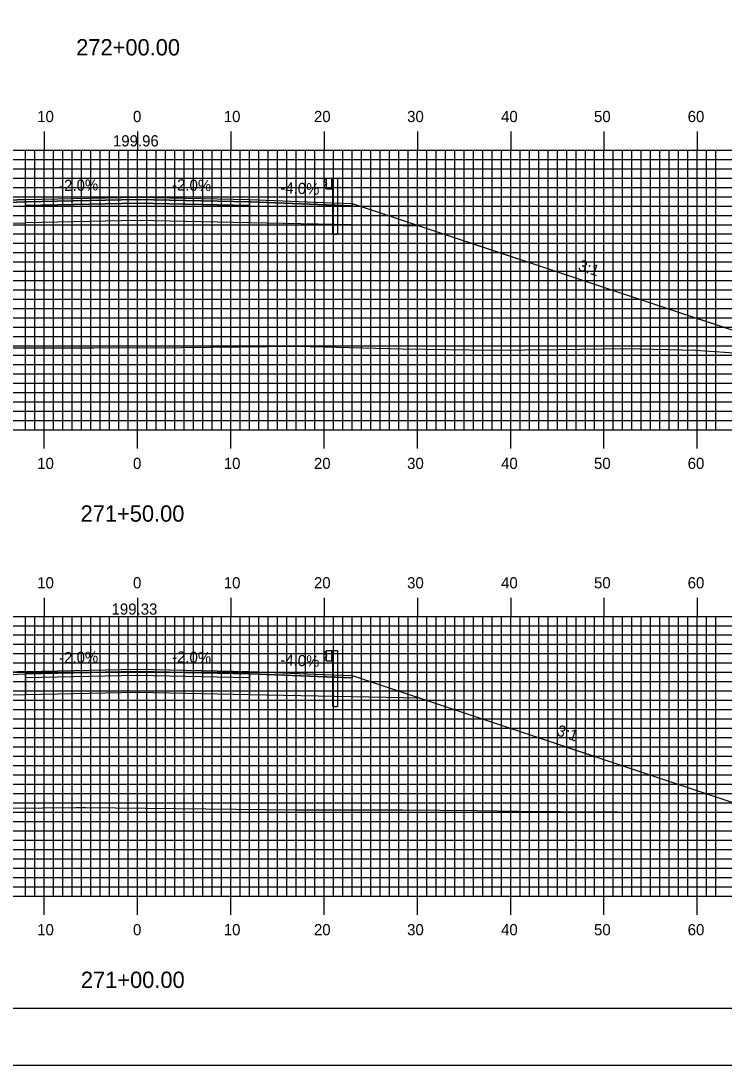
# Model space of a CAD drawing. Extents: x 1808619 to 1808962, y 442591 to 442811.
# Drawn here: x 1808772.3 to 1808847.7, y 442590.5 to 442702.5 of the extents above; entities that cross this region are included whole.
import ezdxf

# ---------------------------------------------------------------- set-up
doc = ezdxf.new("R2010")
doc.units = 0
for name, color, linetype in [('ANNOTATION', 7, 'Continuous'), ('BORDER', 7, 'Continuous'), ('D_Guardrail_Beam_Rt', 7, 'Continuous'), ('D_Roadway_Centerline', 7, 'Continuous'), ('D_Roadway_Centerline_Text', 7, 'Continuous'), ('D_Roadway_Edge_Shoulder', 7, 'Continuous'), ('D_Roadway_Edge_TW', 7, 'Continuous'), ('D_Roadway_Pavement', 7, 'Continuous'), ('D_Roadway_SlopeLines', 7, 'Continuous'), ('D_Roadway_SubGrade', 7, 'Continuous'), ('H_V ANNOTATION', 7, 'Continuous'), ('MAJOR', 7, 'Continuous'), ('MINOR', 7, 'Continuous'), ('PLOT BOUNDARY', 7, 'Continuous'), ('S_Roadway_Centerline', 7, 'Continuous')]:
    doc.layers.add(name, color=color, linetype=linetype)

msp = doc.modelspace()

# ---------------------------------------------------------------- linework, layer by layer
at = {"layer": 'BORDER'}
msp.add_lwpolyline([(1808635.21, 442596.67), (1808955.21, 442596.67), (1808955.21, 442806.67), (1808635.21, 442806.67)], close=True, dxfattribs=at)
at = {"layer": 'D_Guardrail_Beam_Rt'}
for p, q in [((1808804.99, 442685.54), (1808804.85, 442685.44)), ((1808804.85, 442685.3), (1808805.04, 442685.16)), ((1808805.08, 442685.56), (1808805.01, 442685.55)), ((1808805.08, 442685.65), (1808805.77, 442685.65)), ((1808805.08, 442684.48), (1808805.08, 442685.65)), ((1808805.6, 442685.65), (1808805.6, 442684.48)), ((1808805.71, 442685.65), (1808805.71, 442684.48)), ((1808805.77, 442685.65), (1808806.24, 442685.65)), ((1808805.77, 442685.65), (1808805.77, 442684.48)), ((1808806.24, 442685.65), (1808806.24, 442679.65)), ((1808805.04, 442684.96), (1808804.85, 442684.83)), ((1808804.85, 442684.68), (1808804.99, 442684.58)), ((1808805.01, 442684.58), (1808805.08, 442684.56)), ((1808805.08, 442685.1), (1808805.08, 442685.03)), ((1808805.77, 442684.48), (1808805.08, 442684.48)), ((1808805.75, 442679.65), (1808805.75, 442684.48)), ((1808805.75, 442679.65), (1808806.24, 442679.65)), ((1808804.99, 442634.91), (1808804.85, 442634.81)), ((1808805.08, 442634.93), (1808805.01, 442634.92)), ((1808805.08, 442635.02), (1808805.77, 442635.02)), ((1808805.08, 442633.85), (1808805.08, 442635.02)), ((1808805.6, 442635.02), (1808805.6, 442633.85)), ((1808805.71, 442635.02), (1808805.71, 442633.85)), ((1808805.77, 442635.02), (1808806.24, 442635.02)), ((1808805.77, 442635.02), (1808805.77, 442633.85)), ((1808806.24, 442635.02), (1808806.24, 442629.02)), ((1808804.85, 442634.67), (1808805.04, 442634.53)), ((1808805.04, 442634.34), (1808804.85, 442634.2)), ((1808804.85, 442634.06), (1808804.99, 442633.96)), ((1808805.01, 442633.95), (1808805.08, 442633.93)), ((1808805.08, 442634.47), (1808805.08, 442634.4)), ((1808805.77, 442633.85), (1808805.08, 442633.85)), ((1808805.75, 442629.02), (1808805.75, 442633.85)), ((1808805.75, 442629.02), (1808806.24, 442629.02))]:
    msp.add_line(p, q, dxfattribs=at)
for centre, major_axis, start_param, end_param in [((1808804.9, 442685.37), (-0.0877, 0), 5.323254, 7.243116), ((1808805.02, 442685.51), (-0.0417, 0), 4.907132, 5.323254), ((1808804.9, 442684.76), (-0.0877, 0), 5.323254, 7.243116), ((1808805.02, 442684.62), (-0.0417, 0), 0.959931, 1.376053), ((1808805, 442685.1), (0.0789, 0), 0, 0.959931), ((1808805, 442685.03), (0.0789, 0), 5.323254, 6.283185), ((1808804.9, 442634.74), (-0.0877, 0), 5.323254, 7.243116), ((1808805.02, 442634.88), (-0.0417, 0), 4.907132, 5.323254), ((1808804.9, 442634.13), (-0.0877, 0), 5.323254, 7.243116), ((1808805.02, 442633.99), (-0.0417, 0), 0.959931, 1.376053), ((1808805, 442634.47), (0.0789, 0), 0, 0.959931), ((1808805, 442634.4), (0.0789, 0), 5.323254, 6.283185)]:
    msp.add_ellipse(centre, major_axis=major_axis, ratio=0.995501, start_param=start_param, end_param=end_param, dxfattribs=at)
at = {"layer": 'D_Roadway_Centerline'}
for points in [[(1808717.59, 442667.84), (1808754.72, 442680.52), (1808761.81, 442682.94), (1808764.81, 442683.06), (1808772.81, 442683.38), (1808784.81, 442683.62), (1808796.81, 442683.38), (1808804.81, 442683.06), (1808807.81, 442682.94), (1808815.09, 442680.52), (1808856.88, 442666.59)], [(1808713.91, 442618.99), (1808744.23, 442629.09), (1808746.8, 442629.73), (1808756.23, 442632.09), (1808772.81, 442632.75), (1808784.81, 442632.99), (1808796.81, 442632.75), (1808804.81, 442632.43), (1808807.81, 442632.31), (1808815.09, 442629.89), (1808852.27, 442617.49)]]:
    msp.add_lwpolyline(points, dxfattribs=at)
at = {"layer": 'D_Roadway_Edge_Shoulder'}
for points in [[(1808772.81, 442683.38), (1808764.81, 442683.06), (1808764.81, 442683.06), (1808761.81, 442682.94), (1808761.81, 442682.69), (1808772.81, 442683.13)], [(1808796.81, 442683.38), (1808804.81, 442683.06), (1808804.81, 442683.06), (1808807.81, 442682.94), (1808807.81, 442682.69), (1808796.81, 442683.13)], [(1808772.81, 442632.75), (1808756.23, 442632.09), (1808756.23, 442631.84), (1808772.81, 442632.5)], [(1808796.81, 442632.75), (1808804.81, 442632.43), (1808804.81, 442632.43), (1808807.81, 442632.31), (1808807.81, 442632.06), (1808796.81, 442632.5)]]:
    msp.add_lwpolyline(points, close=True, dxfattribs=at)
at = {"layer": 'D_Roadway_Edge_TW'}
for points in [[(1808772.81, 442683.13), (1808772.81, 442683.38), (1808784.81, 442683.62), (1808796.81, 442683.38), (1808796.81, 442683.13), (1808784.81, 442683.37)], [(1808772.81, 442632.5), (1808772.81, 442632.75), (1808784.81, 442632.99), (1808796.81, 442632.75), (1808796.81, 442632.5), (1808784.81, 442632.74)]]:
    msp.add_lwpolyline(points, close=True, dxfattribs=at)
at = {"layer": 'D_Roadway_Pavement'}
for points in [[(1808772.81, 442682.72), (1808772.81, 442683.13), (1808784.81, 442683.37), (1808796.81, 442683.13), (1808796.81, 442682.72), (1808784.81, 442682.96)], [(1808772.81, 442632.09), (1808772.81, 442632.5), (1808784.81, 442632.74), (1808796.81, 442632.5), (1808796.81, 442632.09), (1808784.81, 442632.33)]]:
    msp.add_lwpolyline(points, close=True, dxfattribs=at)
for points in [[(1808772.81, 442683.13), (1808772.81, 442682.72)], [(1808796.81, 442683.13), (1808796.81, 442682.72)]]:
    msp.add_lwpolyline(points, dxfattribs=at)
at = {"layer": 'D_Roadway_SlopeLines'}
for points in [[(1808807.81, 442682.94), (1808856.88, 442666.59)], [(1808807.81, 442632.31), (1808852.27, 442617.49)]]:
    msp.add_lwpolyline(points, dxfattribs=at)
at = {"layer": 'D_Roadway_SubGrade'}
for points in [[(1808772.81, 442682.72), (1808772.81, 442683.13), (1808761.81, 442682.69), (1808761.81, 442682.94), (1808754.72, 442680.52), (1808772.81, 442680.88)], [(1808772.81, 442680.88), (1808772.81, 442683.13), (1808772.81, 442682.72), (1808784.81, 442682.96), (1808796.81, 442682.72), (1808796.81, 442683.13), (1808796.81, 442680.88), (1808784.81, 442681.12)], [(1808796.81, 442682.72), (1808796.81, 442683.13), (1808807.81, 442682.69), (1808807.81, 442682.94), (1808815.09, 442680.52), (1808796.81, 442680.88)], [(1808772.81, 442630.25), (1808772.81, 442632.5), (1808784.81, 442632.74), (1808796.81, 442632.5), (1808796.81, 442630.25), (1808784.81, 442630.49)], [(1808772.81, 442630.25), (1808746.8, 442629.73), (1808756.23, 442632.09), (1808756.23, 442631.84), (1808772.81, 442632.5)], [(1808796.81, 442632.5), (1808807.81, 442632.06), (1808807.81, 442632.31), (1808815.09, 442629.89), (1808796.81, 442630.25)]]:
    msp.add_lwpolyline(points, close=True, dxfattribs=at)
at = {"layer": 'MAJOR'}
for p, q in [((1808774.81, 442690.67), (1808774.81, 442688.67)), ((1808784.81, 442690.67), (1808784.81, 442688.67)), ((1808794.81, 442690.67), (1808794.81, 442688.67)), ((1808804.81, 442690.67), (1808804.81, 442688.67)), ((1808814.81, 442690.67), (1808814.81, 442688.67)), ((1808824.81, 442690.67), (1808824.81, 442688.67)), ((1808834.81, 442690.67), (1808834.81, 442688.67)), ((1808844.81, 442690.67), (1808844.81, 442688.67)), ((1808644.81, 442688.67), (1808924.81, 442688.67)), ((1808644.81, 442688.67), (1808924.81, 442688.67)), ((1808774.81, 442658.67), (1808774.81, 442688.67)), ((1808784.81, 442658.67), (1808784.81, 442688.67)), ((1808794.81, 442658.67), (1808794.81, 442688.67)), ((1808804.81, 442658.67), (1808804.81, 442688.67)), ((1808814.81, 442658.67), (1808814.81, 442688.67)), ((1808824.81, 442658.67), (1808824.81, 442688.67)), ((1808834.81, 442658.67), (1808834.81, 442688.67)), ((1808844.81, 442658.67), (1808844.81, 442688.67)), ((1808644.81, 442683.67), (1808924.81, 442683.67)), ((1808644.81, 442678.67), (1808924.81, 442678.67)), ((1808644.81, 442673.67), (1808924.81, 442673.67)), ((1808644.81, 442668.67), (1808924.81, 442668.67)), ((1808644.81, 442663.67), (1808924.81, 442663.67)), ((1808644.81, 442658.67), (1808924.81, 442658.67)), ((1808644.81, 442658.67), (1808924.81, 442658.67)), ((1808774.81, 442656.66), (1808774.81, 442658.67)), ((1808784.81, 442656.66), (1808784.81, 442658.67)), ((1808794.81, 442656.66), (1808794.81, 442658.67)), ((1808804.81, 442656.66), (1808804.81, 442658.67)), ((1808814.81, 442656.66), (1808814.81, 442658.67)), ((1808824.81, 442656.66), (1808824.81, 442658.67)), ((1808834.81, 442656.66), (1808834.81, 442658.67)), ((1808844.81, 442656.66), (1808844.81, 442658.67)), ((1808774.81, 442640.67), (1808774.81, 442638.67)), ((1808784.81, 442640.67), (1808784.81, 442638.67)), ((1808794.81, 442640.67), (1808794.81, 442638.67)), ((1808804.81, 442640.67), (1808804.81, 442638.67)), ((1808814.81, 442640.67), (1808814.81, 442638.67)), ((1808824.81, 442640.67), (1808824.81, 442638.67)), ((1808834.81, 442640.67), (1808834.81, 442638.67)), ((1808844.81, 442640.67), (1808844.81, 442638.67)), ((1808644.81, 442638.67), (1808924.81, 442638.67)), ((1808644.81, 442638.67), (1808924.81, 442638.67)), ((1808774.81, 442608.67), (1808774.81, 442638.67)), ((1808784.81, 442608.67), (1808784.81, 442638.67)), ((1808794.81, 442608.67), (1808794.81, 442638.67)), ((1808804.81, 442608.67), (1808804.81, 442638.67)), ((1808814.81, 442608.67), (1808814.81, 442638.67)), ((1808824.81, 442608.67), (1808824.81, 442638.67)), ((1808834.81, 442608.67), (1808834.81, 442638.67)), ((1808844.81, 442608.67), (1808844.81, 442638.67)), ((1808644.81, 442633.67), (1808924.81, 442633.67)), ((1808644.81, 442628.67), (1808924.81, 442628.67)), ((1808644.81, 442623.67), (1808924.81, 442623.67)), ((1808644.81, 442618.67), (1808924.81, 442618.67)), ((1808644.81, 442613.67), (1808924.81, 442613.67)), ((1808644.81, 442608.67), (1808924.81, 442608.67)), ((1808644.81, 442608.67), (1808924.81, 442608.67)), ((1808774.81, 442606.66), (1808774.81, 442608.67)), ((1808784.81, 442606.66), (1808784.81, 442608.67)), ((1808794.81, 442606.66), (1808794.81, 442608.67)), ((1808804.81, 442606.66), (1808804.81, 442608.67)), ((1808814.81, 442606.66), (1808814.81, 442608.67)), ((1808824.81, 442606.66), (1808824.81, 442608.67)), ((1808834.81, 442606.66), (1808834.81, 442608.67)), ((1808844.81, 442606.66), (1808844.81, 442608.67))]:
    msp.add_line(p, q, dxfattribs=at)
at = {"layer": 'MINOR'}
for p, q in [((1808772.81, 442658.67), (1808772.81, 442688.67)), ((1808773.81, 442658.67), (1808773.81, 442688.67)), ((1808775.81, 442658.67), (1808775.81, 442688.67)), ((1808776.81, 442658.67), (1808776.81, 442688.67)), ((1808777.81, 442658.67), (1808777.81, 442688.67)), ((1808778.81, 442658.67), (1808778.81, 442688.67)), ((1808779.81, 442658.67), (1808779.81, 442688.67)), ((1808780.81, 442658.67), (1808780.81, 442688.67)), ((1808781.81, 442658.67), (1808781.81, 442688.67)), ((1808782.81, 442658.67), (1808782.81, 442688.67)), ((1808783.81, 442658.67), (1808783.81, 442688.67)), ((1808785.81, 442658.67), (1808785.81, 442688.67)), ((1808786.81, 442658.67), (1808786.81, 442688.67)), ((1808787.81, 442658.67), (1808787.81, 442688.67)), ((1808788.81, 442658.67), (1808788.81, 442688.67)), ((1808789.81, 442658.67), (1808789.81, 442688.67)), ((1808790.81, 442658.67), (1808790.81, 442688.67)), ((1808791.81, 442658.67), (1808791.81, 442688.67)), ((1808792.81, 442658.67), (1808792.81, 442688.67)), ((1808793.81, 442658.67), (1808793.81, 442688.67)), ((1808795.81, 442658.67), (1808795.81, 442688.67)), ((1808796.81, 442658.67), (1808796.81, 442688.67)), ((1808797.81, 442658.67), (1808797.81, 442688.67)), ((1808798.81, 442658.67), (1808798.81, 442688.67)), ((1808799.81, 442658.67), (1808799.81, 442688.67)), ((1808800.81, 442658.67), (1808800.81, 442688.67)), ((1808801.81, 442658.67), (1808801.81, 442688.67)), ((1808802.81, 442658.67), (1808802.81, 442688.67)), ((1808803.81, 442658.67), (1808803.81, 442688.67)), ((1808805.81, 442658.67), (1808805.81, 442688.67)), ((1808806.81, 442658.67), (1808806.81, 442688.67)), ((1808807.81, 442658.67), (1808807.81, 442688.67)), ((1808808.81, 442658.67), (1808808.81, 442688.67)), ((1808809.81, 442658.67), (1808809.81, 442688.67)), ((1808810.81, 442658.67), (1808810.81, 442688.67)), ((1808811.81, 442658.67), (1808811.81, 442688.67)), ((1808812.81, 442658.67), (1808812.81, 442688.67)), ((1808813.81, 442658.67), (1808813.81, 442688.67)), ((1808815.81, 442658.67), (1808815.81, 442688.67)), ((1808816.81, 442658.67), (1808816.81, 442688.67)), ((1808817.81, 442658.67), (1808817.81, 442688.67)), ((1808818.81, 442658.67), (1808818.81, 442688.67)), ((1808819.81, 442658.67), (1808819.81, 442688.67)), ((1808820.81, 442658.67), (1808820.81, 442688.67)), ((1808821.81, 442658.67), (1808821.81, 442688.67)), ((1808822.81, 442658.67), (1808822.81, 442688.67)), ((1808823.81, 442658.67), (1808823.81, 442688.67)), ((1808825.81, 442658.67), (1808825.81, 442688.67)), ((1808826.81, 442658.67), (1808826.81, 442688.67)), ((1808827.81, 442658.67), (1808827.81, 442688.67)), ((1808828.81, 442658.67), (1808828.81, 442688.67)), ((1808829.81, 442658.67), (1808829.81, 442688.67)), ((1808830.81, 442658.67), (1808830.81, 442688.67)), ((1808831.81, 442658.67), (1808831.81, 442688.67)), ((1808832.81, 442658.67), (1808832.81, 442688.67)), ((1808833.81, 442658.67), (1808833.81, 442688.67)), ((1808835.81, 442658.67), (1808835.81, 442688.67)), ((1808836.81, 442658.67), (1808836.81, 442688.67)), ((1808837.81, 442658.67), (1808837.81, 442688.67)), ((1808838.81, 442658.67), (1808838.81, 442688.67)), ((1808839.81, 442658.67), (1808839.81, 442688.67)), ((1808840.81, 442658.67), (1808840.81, 442688.67)), ((1808841.81, 442658.67), (1808841.81, 442688.67)), ((1808842.81, 442658.67), (1808842.81, 442688.67)), ((1808843.81, 442658.67), (1808843.81, 442688.67)), ((1808845.81, 442658.67), (1808845.81, 442688.67)), ((1808846.81, 442658.67), (1808846.81, 442688.67)), ((1808644.81, 442687.67), (1808924.81, 442687.67)), ((1808644.81, 442686.67), (1808924.81, 442686.67)), ((1808644.81, 442685.67), (1808924.81, 442685.67)), ((1808644.81, 442684.67), (1808924.81, 442684.67)), ((1808644.81, 442682.67), (1808924.81, 442682.67)), ((1808644.81, 442681.67), (1808924.81, 442681.67)), ((1808644.81, 442680.67), (1808924.81, 442680.67)), ((1808644.81, 442679.67), (1808924.81, 442679.67)), ((1808644.81, 442677.67), (1808924.81, 442677.67)), ((1808644.81, 442676.67), (1808924.81, 442676.67)), ((1808644.81, 442675.67), (1808924.81, 442675.67)), ((1808644.81, 442674.67), (1808924.81, 442674.67)), ((1808644.81, 442672.67), (1808924.81, 442672.67)), ((1808644.81, 442671.67), (1808924.81, 442671.67)), ((1808644.81, 442670.67), (1808924.81, 442670.67)), ((1808644.81, 442669.67), (1808924.81, 442669.67)), ((1808644.81, 442667.67), (1808924.81, 442667.67)), ((1808644.81, 442666.67), (1808924.81, 442666.67)), ((1808644.81, 442665.67), (1808924.81, 442665.67)), ((1808644.81, 442664.67), (1808924.81, 442664.67)), ((1808644.81, 442662.67), (1808924.81, 442662.67)), ((1808644.81, 442661.67), (1808924.81, 442661.67)), ((1808644.81, 442660.67), (1808924.81, 442660.67)), ((1808644.81, 442659.67), (1808924.81, 442659.67)), ((1808772.81, 442608.67), (1808772.81, 442638.67)), ((1808773.81, 442608.67), (1808773.81, 442638.67)), ((1808775.81, 442608.67), (1808775.81, 442638.67)), ((1808776.81, 442608.67), (1808776.81, 442638.67)), ((1808777.81, 442608.67), (1808777.81, 442638.67)), ((1808778.81, 442608.67), (1808778.81, 442638.67)), ((1808779.81, 442608.67), (1808779.81, 442638.67)), ((1808780.81, 442608.67), (1808780.81, 442638.67)), ((1808781.81, 442608.67), (1808781.81, 442638.67)), ((1808782.81, 442608.67), (1808782.81, 442638.67)), ((1808783.81, 442608.67), (1808783.81, 442638.67)), ((1808785.81, 442608.67), (1808785.81, 442638.67)), ((1808786.81, 442608.67), (1808786.81, 442638.67)), ((1808787.81, 442608.67), (1808787.81, 442638.67)), ((1808788.81, 442608.67), (1808788.81, 442638.67)), ((1808789.81, 442608.67), (1808789.81, 442638.67)), ((1808790.81, 442608.67), (1808790.81, 442638.67)), ((1808791.81, 442608.67), (1808791.81, 442638.67)), ((1808792.81, 442608.67), (1808792.81, 442638.67)), ((1808793.81, 442608.67), (1808793.81, 442638.67)), ((1808795.81, 442608.67), (1808795.81, 442638.67)), ((1808796.81, 442608.67), (1808796.81, 442638.67)), ((1808797.81, 442608.67), (1808797.81, 442638.67)), ((1808798.81, 442608.67), (1808798.81, 442638.67)), ((1808799.81, 442608.67), (1808799.81, 442638.67)), ((1808800.81, 442608.67), (1808800.81, 442638.67)), ((1808801.81, 442608.67), (1808801.81, 442638.67)), ((1808802.81, 442608.67), (1808802.81, 442638.67)), ((1808803.81, 442608.67), (1808803.81, 442638.67)), ((1808805.81, 442608.67), (1808805.81, 442638.67)), ((1808806.81, 442608.67), (1808806.81, 442638.67)), ((1808807.81, 442608.67), (1808807.81, 442638.67)), ((1808808.81, 442608.67), (1808808.81, 442638.67)), ((1808809.81, 442608.67), (1808809.81, 442638.67)), ((1808810.81, 442608.67), (1808810.81, 442638.67)), ((1808811.81, 442608.67), (1808811.81, 442638.67)), ((1808812.81, 442608.67), (1808812.81, 442638.67)), ((1808813.81, 442608.67), (1808813.81, 442638.67)), ((1808815.81, 442608.67), (1808815.81, 442638.67)), ((1808816.81, 442608.67), (1808816.81, 442638.67)), ((1808817.81, 442608.67), (1808817.81, 442638.67)), ((1808818.81, 442608.67), (1808818.81, 442638.67)), ((1808819.81, 442608.67), (1808819.81, 442638.67)), ((1808820.81, 442608.67), (1808820.81, 442638.67)), ((1808821.81, 442608.67), (1808821.81, 442638.67)), ((1808822.81, 442608.67), (1808822.81, 442638.67)), ((1808823.81, 442608.67), (1808823.81, 442638.67)), ((1808825.81, 442608.67), (1808825.81, 442638.67)), ((1808826.81, 442608.67), (1808826.81, 442638.67)), ((1808827.81, 442608.67), (1808827.81, 442638.67)), ((1808828.81, 442608.67), (1808828.81, 442638.67)), ((1808829.81, 442608.67), (1808829.81, 442638.67)), ((1808830.81, 442608.67), (1808830.81, 442638.67)), ((1808831.81, 442608.67), (1808831.81, 442638.67)), ((1808832.81, 442608.67), (1808832.81, 442638.67)), ((1808833.81, 442608.67), (1808833.81, 442638.67)), ((1808835.81, 442608.67), (1808835.81, 442638.67)), ((1808836.81, 442608.67), (1808836.81, 442638.67)), ((1808837.81, 442608.67), (1808837.81, 442638.67)), ((1808838.81, 442608.67), (1808838.81, 442638.67)), ((1808839.81, 442608.67), (1808839.81, 442638.67)), ((1808840.81, 442608.67), (1808840.81, 442638.67)), ((1808841.81, 442608.67), (1808841.81, 442638.67)), ((1808842.81, 442608.67), (1808842.81, 442638.67)), ((1808843.81, 442608.67), (1808843.81, 442638.67)), ((1808845.81, 442608.67), (1808845.81, 442638.67)), ((1808846.81, 442608.67), (1808846.81, 442638.67)), ((1808644.81, 442637.67), (1808924.81, 442637.67)), ((1808644.81, 442636.67), (1808924.81, 442636.67)), ((1808644.81, 442635.67), (1808924.81, 442635.67)), ((1808644.81, 442634.67), (1808924.81, 442634.67)), ((1808644.81, 442632.67), (1808924.81, 442632.67)), ((1808644.81, 442631.67), (1808924.81, 442631.67)), ((1808644.81, 442630.67), (1808924.81, 442630.67)), ((1808644.81, 442629.67), (1808924.81, 442629.67)), ((1808644.81, 442627.67), (1808924.81, 442627.67)), ((1808644.81, 442626.67), (1808924.81, 442626.67)), ((1808644.81, 442625.67), (1808924.81, 442625.67)), ((1808644.81, 442624.67), (1808924.81, 442624.67)), ((1808644.81, 442622.67), (1808924.81, 442622.67)), ((1808644.81, 442621.67), (1808924.81, 442621.67)), ((1808644.81, 442620.67), (1808924.81, 442620.67)), ((1808644.81, 442619.67), (1808924.81, 442619.67)), ((1808644.81, 442617.67), (1808924.81, 442617.67)), ((1808644.81, 442616.67), (1808924.81, 442616.67)), ((1808644.81, 442615.67), (1808924.81, 442615.67)), ((1808644.81, 442614.67), (1808924.81, 442614.67)), ((1808644.81, 442612.67), (1808924.81, 442612.67)), ((1808644.81, 442611.67), (1808924.81, 442611.67)), ((1808644.81, 442610.67), (1808924.81, 442610.67)), ((1808644.81, 442609.67), (1808924.81, 442609.67))]:
    msp.add_line(p, q, dxfattribs=at)
at = {"layer": 'PLOT BOUNDARY'}
msp.add_lwpolyline([(1808619.02, 442590.55), (1808959.02, 442590.55), (1808959.02, 442810.55), (1808619.02, 442810.55)], close=True, dxfattribs=at)
at = {"layer": 'S_Roadway_Centerline'}
for points in [[(1808709.22, 442667.91), (1808717.51, 442667.84), (1808724.9, 442668.06), (1808735.75, 442667.34), (1808738.89, 442667.25), (1808751.13, 442667.29), (1808759.46, 442667.33), (1808760.52, 442667.35), (1808761.85, 442667.38), (1808771.44, 442667.46), (1808780.13, 442667.45), (1808783.17, 442667.5), (1808786.43, 442667.48), (1808801.93, 442667.63), (1808813.18, 442667.36), (1808822.82, 442667.23), (1808829.77, 442667.27), (1808837.17, 442667.39), (1808844.63, 442667.21), (1808852.92, 442666.65)], [(1808708.64, 442619.1), (1808715.38, 442618.95), (1808726.62, 442618.55), (1808731.77, 442618.4), (1808735.39, 442618.27), (1808756, 442618.03), (1808758.06, 442618.05), (1808774.64, 442618.14), (1808778.23, 442618.18), (1808779.24, 442618.16), (1808801.78, 442617.92), (1808801.97, 442617.91), (1808813.21, 442617.92), (1808821.21, 442617.86), (1808825.6, 442617.78), (1808830.16, 442617.76), (1808842.48, 442617.66), (1808848.6, 442617.62)]]:
    msp.add_lwpolyline(points, dxfattribs=at)

# ---------------------------------------------------------------- texts
at = {"layer": 'ANNOTATION'}
for s, rotation, p in [('-2.0%', 1.1458, (1808776.42, 442684.26)), ('-2.0%', 358.8542, (1808788.5, 442684.35)), ('-4.0%', 357.7094, (1808800.1, 442684.05)), ('3:1', 341.5651, (1808831.95, 442675.81)), ('-2.0%', 1.1458, (1808776.42, 442633.63)), ('-2.0%', 358.8542, (1808788.5, 442633.72)), ('-4.0%', 357.7094, (1808800.1, 442633.42)), ('3:1', 341.5651, (1808829.65, 442625.94))]:
    msp.add_text(s, height=1.2, rotation=rotation, dxfattribs=at).set_placement(p)
at = {"layer": 'D_Roadway_Centerline'}
for s, p in [('C', (1808784.81, 442683.62)), ('L', (1808784.81, 442683.62)), ('C', (1808784.81, 442632.99)), ('L', (1808784.81, 442632.99))]:
    msp.add_text(s, height=0.0146, dxfattribs=at).set_placement(p)
at = {"layer": 'D_Roadway_Centerline_Text'}
for s, p in [('199.96', (1808782.18, 442689.06)), ('199.33', (1808782.03, 442638.85))]:
    msp.add_text(s, height=1.2, dxfattribs=at).set_placement(p)
at = {"layer": 'H_V ANNOTATION'}
for s, height, p in [('272+00.00', 1.75, (1808778.24, 442698.82)), ('10', 1.2, (1808774.06, 442691.67)), ('0', 1.2, (1808784.33, 442691.67)), ('10', 1.2, (1808794.06, 442691.67)), ('20', 1.2, (1808803.72, 442691.67)), ('30', 1.2, (1808813.71, 442691.67)), ('40', 1.2, (1808823.78, 442691.67)), ('50', 1.2, (1808833.74, 442691.67)), ('60', 1.2, (1808843.78, 442691.67)), ('10', 1.2, (1808774.06, 442654.47)), ('0', 1.2, (1808784.33, 442654.47)), ('10', 1.2, (1808794.06, 442654.47)), ('20', 1.2, (1808803.72, 442654.47)), ('30', 1.2, (1808813.71, 442654.47)), ('40', 1.2, (1808823.78, 442654.47)), ('50', 1.2, (1808833.74, 442654.47)), ('60', 1.2, (1808843.78, 442654.47)), ('271+50.00', 1.75, (1808778.71, 442648.82)), ('10', 1.2, (1808774.06, 442641.67)), ('0', 1.2, (1808784.33, 442641.67)), ('10', 1.2, (1808794.06, 442641.67)), ('20', 1.2, (1808803.72, 442641.67)), ('30', 1.2, (1808813.71, 442641.67)), ('40', 1.2, (1808823.78, 442641.67)), ('50', 1.2, (1808833.74, 442641.67)), ('60', 1.2, (1808843.78, 442641.67)), ('10', 1.2, (1808774.06, 442604.47)), ('0', 1.2, (1808784.33, 442604.47)), ('10', 1.2, (1808794.06, 442604.47)), ('20', 1.2, (1808803.72, 442604.47)), ('30', 1.2, (1808813.71, 442604.47)), ('40', 1.2, (1808823.78, 442604.47)), ('50', 1.2, (1808833.74, 442604.47)), ('60', 1.2, (1808843.78, 442604.47)), ('271+00.00', 1.75, (1808778.74, 442598.82))]:
    msp.add_text(s, height=height, dxfattribs=at).set_placement(p)

doc.saveas('drawing.dxf')
